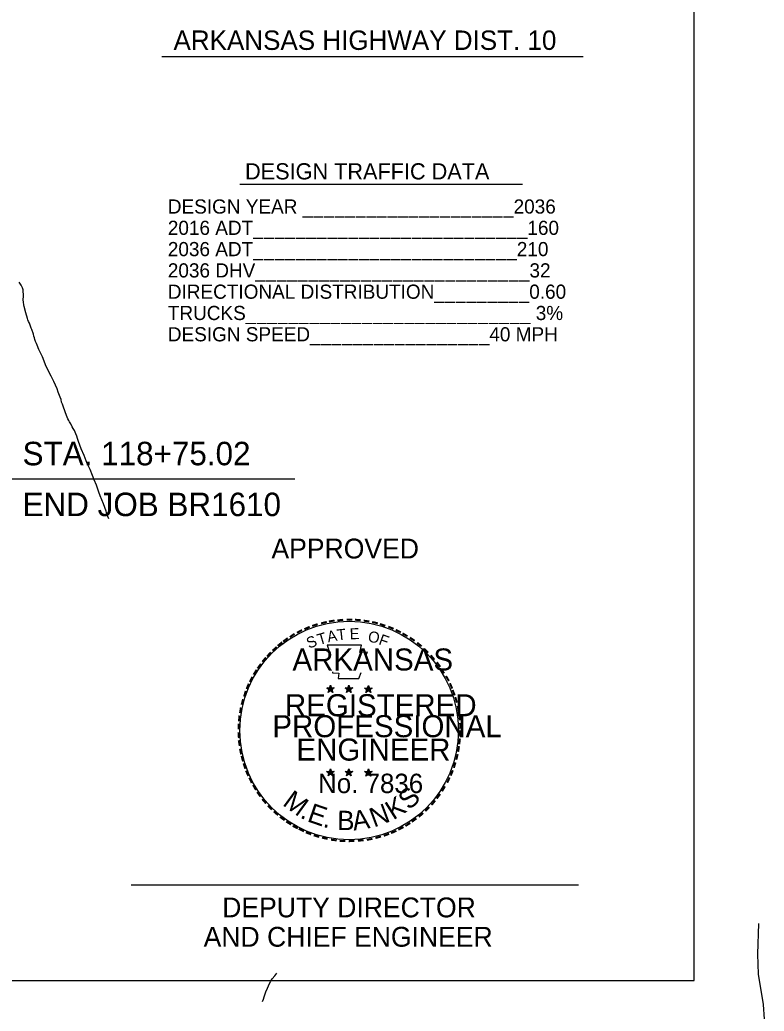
# Model space of a CAD drawing. Extents: x 1671357 to 13005564, y 567358 to 14261451.
# Drawn here: x 12758310.29 to 12758319.47, y 14259937.97 to 14259950.22 of the extents above; entities that cross this region are included whole.
import ezdxf

# ---------------------------------------------------------------- set-up
doc = ezdxf.new("R2010")
doc.units = 0
for name, color, linetype in [('32', 7, 'Continuous'), ('43', 7, 'Continuous'), ('Default', 7, 'Continuous'), ('R_Border PE', 7, 'Continuous')]:
    doc.layers.add(name, color=color, linetype=linetype)

msp = doc.modelspace()

# ---------------------------------------------------------------- linework, layer by layer
at = {"layer": '32'}
msp.add_lwpolyline([(12758313.281, 14259938.094), (12758313.294, 14259938.123), (12758313.303, 14259938.149), (12758313.311, 14259938.174), (12758313.323, 14259938.211), (12758313.344, 14259938.26), (12758313.355, 14259938.288), (12758313.382, 14259938.342), (12758313.403, 14259938.373), (12758313.436, 14259938.411), (12758313.459, 14259938.443)], dxfattribs=at)
at = {"layer": '43'}
msp.add_lwpolyline([(12758319.406, 14259939.056), (12758319.392, 14259938.677), (12758319.402, 14259938.43), (12758319.464, 14259938.058), (12758319.474, 14259937.874)], dxfattribs=at)
at = {"layer": 'Default'}
for p, q in [((12758318.61, 14259938.354), (12758318.61, 14259959.371)), ((12758312.04, 14259949.768), (12758317.239, 14259949.768)), ((12758313.002, 14259948.19), (12758316.492, 14259948.19)), ((12758310.042, 14259944.551), (12758313.682, 14259944.551)), ((12758284.583, 14259938.354), (12758318.61, 14259938.354))]:
    msp.add_line(p, q, dxfattribs=at)
for points in [[(12758310.977, 14259945.106), (12758310.969, 14259945.126), (12758310.96, 14259945.145), (12758310.947, 14259945.17), (12758310.933, 14259945.194), (12758310.917, 14259945.228), (12758310.901, 14259945.253), (12758310.891, 14259945.271), (12758310.881, 14259945.291), (12758310.865, 14259945.33), (12758310.847, 14259945.376), (12758310.821, 14259945.447), (12758310.814, 14259945.47), (12758310.802, 14259945.497), (12758310.796, 14259945.529), (12758310.787, 14259945.557), (12758310.761, 14259945.619), (12758310.747, 14259945.662), (12758310.729, 14259945.705), (12758310.708, 14259945.753), (12758310.673, 14259945.817), (12758310.614, 14259945.937), (12758310.566, 14259946.056), (12758310.523, 14259946.148), (12758310.501, 14259946.2), (12758310.493, 14259946.221), (12758310.482, 14259946.248), (12758310.473, 14259946.271), (12758310.467, 14259946.292), (12758310.46, 14259946.314), (12758310.454, 14259946.335), (12758310.435, 14259946.394), (12758310.429, 14259946.412), (12758310.424, 14259946.423), (12758310.406, 14259946.473), (12758310.396, 14259946.492), (12758310.387, 14259946.514), (12758310.382, 14259946.532), (12758310.363, 14259946.599), (12758310.342, 14259946.678), (12758310.338, 14259946.698), (12758310.332, 14259946.733), (12758310.33, 14259946.761), (12758310.33, 14259946.774), (12758310.331, 14259946.792), (12758310.332, 14259946.801), (12758310.332, 14259946.825), (12758310.33, 14259946.863), (12758310.327, 14259946.885), (12758310.323, 14259946.896), (12758310.319, 14259946.907), (12758310.311, 14259946.925), (12758310.302, 14259946.941), (12758310.278, 14259946.979)], [(12758311.244, 14259944.435), (12758311.232, 14259944.471), (12758311.204, 14259944.537), (12758311.183, 14259944.592), (12758311.154, 14259944.663), (12758311.119, 14259944.74), (12758311.082, 14259944.838), (12758311.045, 14259944.922), (12758311.013, 14259945.009), (12758311, 14259945.047), (12758310.99, 14259945.075), (12758310.977, 14259945.106)], [(12758311.385, 14259944.055), (12758311.375, 14259944.086), (12758311.369, 14259944.106), (12758311.357, 14259944.135), (12758311.351, 14259944.152), (12758311.32, 14259944.239), (12758311.28, 14259944.341), (12758311.262, 14259944.387), (12758311.244, 14259944.435)]]:
    msp.add_lwpolyline(points, dxfattribs=at)
at = {"layer": 'R_Border PE'}
for p, q in [((12758314.075, 14259941.966), (12758314.122, 14259941.951)), ((12758314.075, 14259941.966), (12758314.11, 14259941.96)), ((12758314.075, 14259941.966), (12758314.107, 14259941.949)), ((12758314.122, 14259942.001), (12758314.117, 14259941.966)), ((12758314.122, 14259941.951), (12758314.122, 14259942.001)), ((12758314.122, 14259942.001), (12758314.129, 14259941.967)), ((12758314.168, 14259941.966), (12758314.122, 14259941.951)), ((12758314.168, 14259941.966), (12758314.131, 14259941.959)), ((12758314.168, 14259941.966), (12758314.142, 14259941.952)), ((12758314.303, 14259941.966), (12758314.35, 14259941.951)), ((12758314.303, 14259941.966), (12758314.336, 14259941.96)), ((12758314.303, 14259941.966), (12758314.334, 14259941.949)), ((12758314.35, 14259942.001), (12758314.345, 14259941.966)), ((12758314.35, 14259941.951), (12758314.35, 14259942.001)), ((12758314.35, 14259942.001), (12758314.356, 14259941.967)), ((12758314.397, 14259941.966), (12758314.35, 14259941.951)), ((12758314.397, 14259941.966), (12758314.357, 14259941.959)), ((12758314.397, 14259941.966), (12758314.369, 14259941.952)), ((12758314.542, 14259941.965), (12758314.59, 14259941.949)), ((12758314.542, 14259941.965), (12758314.576, 14259941.958)), ((12758314.542, 14259941.965), (12758314.574, 14259941.948)), ((12758314.59, 14259941.998), (12758314.584, 14259941.965)), ((12758314.59, 14259941.949), (12758314.59, 14259941.998)), ((12758314.59, 14259941.998), (12758314.595, 14259941.965)), ((12758314.637, 14259941.965), (12758314.59, 14259941.949)), ((12758314.637, 14259941.965), (12758314.597, 14259941.958)), ((12758314.637, 14259941.965), (12758314.608, 14259941.951)), ((12758314.093, 14259941.91), (12758314.122, 14259941.951)), ((12758314.093, 14259941.91), (12758314.11, 14259941.944)), ((12758314.093, 14259941.91), (12758314.121, 14259941.939)), ((12758314.152, 14259941.91), (12758314.121, 14259941.939)), ((12758314.152, 14259941.91), (12758314.122, 14259941.951)), ((12758314.152, 14259941.91), (12758314.132, 14259941.949)), ((12758314.32, 14259941.91), (12758314.35, 14259941.951)), ((12758314.32, 14259941.91), (12758314.338, 14259941.944)), ((12758314.32, 14259941.91), (12758314.349, 14259941.939)), ((12758314.378, 14259941.91), (12758314.349, 14259941.939)), ((12758314.378, 14259941.91), (12758314.35, 14259941.951)), ((12758314.378, 14259941.91), (12758314.359, 14259941.949)), ((12758314.559, 14259941.909), (12758314.59, 14259941.949)), ((12758314.559, 14259941.909), (12758314.577, 14259941.942)), ((12758314.559, 14259941.909), (12758314.59, 14259941.938)), ((12758314.618, 14259941.909), (12758314.59, 14259941.949)), ((12758314.618, 14259941.909), (12758314.59, 14259941.938)), ((12758314.618, 14259941.909), (12758314.6, 14259941.948)), ((12758314.073, 14259940.936), (12758314.121, 14259940.92)), ((12758314.073, 14259940.936), (12758314.11, 14259940.929)), ((12758314.073, 14259940.936), (12758314.107, 14259940.919)), ((12758314.093, 14259940.88), (12758314.121, 14259940.92)), ((12758314.093, 14259940.88), (12758314.11, 14259940.913)), ((12758314.093, 14259940.88), (12758314.121, 14259940.91)), ((12758314.121, 14259940.969), (12758314.115, 14259940.936)), ((12758314.121, 14259940.92), (12758314.121, 14259940.969)), ((12758314.121, 14259940.969), (12758314.128, 14259940.936)), ((12758314.168, 14259940.936), (12758314.121, 14259940.92)), ((12758314.152, 14259940.88), (12758314.121, 14259940.92)), ((12758314.152, 14259940.88), (12758314.121, 14259940.909)), ((12758314.168, 14259940.936), (12758314.129, 14259940.929)), ((12758314.152, 14259940.88), (12758314.132, 14259940.919)), ((12758314.168, 14259940.936), (12758314.142, 14259940.922)), ((12758314.301, 14259940.936), (12758314.349, 14259940.92)), ((12758314.301, 14259940.936), (12758314.336, 14259940.929)), ((12758314.301, 14259940.936), (12758314.334, 14259940.919)), ((12758314.32, 14259940.88), (12758314.349, 14259940.92)), ((12758314.32, 14259940.88), (12758314.336, 14259940.913)), ((12758314.32, 14259940.88), (12758314.349, 14259940.91)), ((12758314.349, 14259940.969), (12758314.343, 14259940.936)), ((12758314.349, 14259940.92), (12758314.349, 14259940.969)), ((12758314.349, 14259940.969), (12758314.355, 14259940.936)), ((12758314.397, 14259940.936), (12758314.349, 14259940.92)), ((12758314.377, 14259940.88), (12758314.349, 14259940.92)), ((12758314.377, 14259940.88), (12758314.349, 14259940.909)), ((12758314.397, 14259940.936), (12758314.356, 14259940.929)), ((12758314.377, 14259940.88), (12758314.359, 14259940.919)), ((12758314.397, 14259940.936), (12758314.367, 14259940.922)), ((12758314.542, 14259940.934), (12758314.59, 14259940.919)), ((12758314.542, 14259940.934), (12758314.576, 14259940.927)), ((12758314.542, 14259940.934), (12758314.574, 14259940.917)), ((12758314.559, 14259940.878), (12758314.59, 14259940.919)), ((12758314.559, 14259940.878), (12758314.577, 14259940.912)), ((12758314.559, 14259940.878), (12758314.59, 14259940.909)), ((12758314.59, 14259940.968), (12758314.584, 14259940.934)), ((12758314.59, 14259940.919), (12758314.59, 14259940.968)), ((12758314.59, 14259940.968), (12758314.595, 14259940.934)), ((12758314.637, 14259940.934), (12758314.59, 14259940.919)), ((12758314.618, 14259940.878), (12758314.59, 14259940.919)), ((12758314.618, 14259940.878), (12758314.59, 14259940.908)), ((12758314.637, 14259940.934), (12758314.597, 14259940.927)), ((12758314.618, 14259940.878), (12758314.598, 14259940.917)), ((12758314.637, 14259940.934), (12758314.608, 14259940.92)), ((12758311.662, 14259939.536), (12758317.183, 14259939.536))]:
    msp.add_line(p, q, dxfattribs=at)
for points in [[(12758314.08, 14259942.494), (12758314.117, 14259942.38)], [(12758314.558, 14259942.369), (12758314.577, 14259942.407), (12758314.485, 14259942.404), (12758314.503, 14259942.494), (12758314.08, 14259942.494)], [(12758314.147, 14259942.165), (12758314.147, 14259942.152), (12758314.223, 14259942.149), (12758314.216, 14259942.085), (12758314.471, 14259942.085), (12758314.499, 14259942.158)], [(12758314.122, 14259942.001), (12758314.152, 14259941.91), (12758314.075, 14259941.966), (12758314.168, 14259941.966), (12758314.093, 14259941.91), (12758314.122, 14259942.001)], [(12758314.35, 14259942.001), (12758314.378, 14259941.91), (12758314.303, 14259941.966), (12758314.397, 14259941.966), (12758314.32, 14259941.91), (12758314.35, 14259942.001)], [(12758314.59, 14259941.998), (12758314.618, 14259941.909), (12758314.542, 14259941.965), (12758314.637, 14259941.965), (12758314.559, 14259941.909), (12758314.59, 14259941.998)], [(12758314.121, 14259940.969), (12758314.152, 14259940.88), (12758314.073, 14259940.936), (12758314.168, 14259940.936), (12758314.093, 14259940.88), (12758314.121, 14259940.969)], [(12758314.349, 14259940.969), (12758314.377, 14259940.88), (12758314.301, 14259940.936), (12758314.397, 14259940.936), (12758314.32, 14259940.88), (12758314.349, 14259940.969)], [(12758314.59, 14259940.968), (12758314.618, 14259940.878), (12758314.542, 14259940.934), (12758314.637, 14259940.934), (12758314.559, 14259940.878), (12758314.59, 14259940.968)]]:
    msp.add_lwpolyline(points, dxfattribs=at)
for centre, radius in [((12758314.352, 14259941.441), 1.35), ((12758314.121, 14259941.95), 0.0234), ((12758314.121, 14259941.95), 0.0197), ((12758314.121, 14259941.95), 0.0158), ((12758314.121, 14259941.95), 0.0135), ((12758314.121, 14259941.95), 0.0102), ((12758314.121, 14259941.95), 0.00674), ((12758314.121, 14259941.95), 0.00403), ((12758314.348, 14259941.95), 0.0234), ((12758314.348, 14259941.95), 0.0197), ((12758314.348, 14259941.95), 0.0158), ((12758314.348, 14259941.95), 0.0135), ((12758314.348, 14259941.95), 0.0102), ((12758314.348, 14259941.95), 0.00674), ((12758314.348, 14259941.95), 0.00403), ((12758314.588, 14259941.949), 0.0234), ((12758314.588, 14259941.949), 0.0197), ((12758314.588, 14259941.949), 0.0158), ((12758314.588, 14259941.949), 0.0135), ((12758314.588, 14259941.949), 0.0102), ((12758314.588, 14259941.949), 0.00674), ((12758314.588, 14259941.949), 0.00403), ((12758314.12, 14259940.92), 0.0234), ((12758314.12, 14259940.92), 0.0197), ((12758314.12, 14259940.92), 0.0158), ((12758314.12, 14259940.92), 0.0135), ((12758314.12, 14259940.92), 0.0102), ((12758314.12, 14259940.92), 0.00674), ((12758314.12, 14259940.92), 0.00403), ((12758314.348, 14259940.92), 0.0234), ((12758314.348, 14259940.92), 0.0197), ((12758314.348, 14259940.92), 0.0158), ((12758314.348, 14259940.92), 0.0135), ((12758314.348, 14259940.92), 0.0102), ((12758314.348, 14259940.92), 0.00674), ((12758314.348, 14259940.92), 0.00403), ((12758314.588, 14259940.918), 0.0234), ((12758314.588, 14259940.918), 0.0197), ((12758314.588, 14259940.918), 0.0158), ((12758314.588, 14259940.918), 0.0135), ((12758314.588, 14259940.918), 0.0102), ((12758314.588, 14259940.918), 0.00674), ((12758314.588, 14259940.918), 0.00403)]:
    msp.add_circle(centre, radius, dxfattribs=at)

# ---------------------------------------------------------------- texts
at = {"layer": 'Default'}
for s, height, p in [('ARKANSAS HIGHWAY DIST. 10', 0.24, (12758312.184, 14259949.848)), ('DESIGN TRAFFIC DATA', 0.2, (12758313.067, 14259948.248)), ('DESIGN YEAR ____________________2036', 0.175, (12758312.114, 14259947.826)), ('2016 ADT__________________________160', 0.175, (12758312.114, 14259947.563)), ('2036 ADT_________________________210', 0.175, (12758312.114, 14259947.3)), ('2036 DHV__________________________32', 0.175, (12758312.114, 14259947.037)), ('DIRECTIONAL DISTRIBUTION_________0.60', 0.175, (12758312.114, 14259946.774)), ('TRUCKS___________________________ 3%', 0.175, (12758312.114, 14259946.511)), ('DESIGN SPEED_________________40 MPH', 0.175, (12758312.114, 14259946.248)), ('STA. 118+75.02', 0.29, (12758310.321, 14259944.717)), ('END JOB BR1610', 0.29, (12758310.321, 14259944.089))]:
    msp.add_text(s, height=height, dxfattribs=at).set_placement(p)
at = {"layer": 'R_Border PE'}
for s, height, p in [('APPROVED', 0.245, (12758313.393, 14259943.566)), ('ARKANSAS', 0.2722, (12758313.652, 14259942.182)), ('REGISTERED', 0.2722, (12758313.559, 14259941.617)), ('PROFESSIONAL', 0.27219, (12758313.404, 14259941.358)), ('ENGINEER', 0.2722, (12758313.701, 14259941.069)), ('No. 7836', 0.2391, (12758313.968, 14259940.668)), ('DEPUTY DIRECTOR', 0.24497, (12758312.785, 14259939.133)), ('AND CHIEF ENGINEER', 0.24497, (12758312.556, 14259938.77))]:
    msp.add_text(s, height=height, dxfattribs=at).set_placement(p)
for s, height, rotation, p in [('-', 0.218, 10.2193, (12758314.104, 14259942.702)), ('-', 0.218, 5.8968, (12758314.203, 14259942.716)), ('-', 0.218, 0.1862, (12758314.308, 14259942.726)), ('-', 0.218, 357.743, (12758314.406, 14259942.725)), ('-', 0.218, 28.7918, (12758313.737, 14259942.568)), ('-', 0.218, 24.3072, (12758313.823, 14259942.611)), ('-', 0.218, 19.1761, (12758313.911, 14259942.648)), ('-', 0.218, 13.6301, (12758314.013, 14259942.68)), ('T', 0.136, 6.0228, (12758314.208, 14259942.553)), ('E', 0.136, 0.8323, (12758314.359, 14259942.568)), ('-', 0.218, 352.1617, (12758314.507, 14259942.716)), ('-', 0.218, 347.2049, (12758314.605, 14259942.702)), ('-', 0.218, 342.3362, (12758314.693, 14259942.68)), ('-', 0.218, 337.8551, (12758314.791, 14259942.651)), ('-', 0.218, 334.1211, (12758314.878, 14259942.614)), ('-', 0.218, 36.2317, (12758313.576, 14259942.464)), ('-', 0.218, 34.0636, (12758313.656, 14259942.518)), ('S', 0.136, 21.594, (12758313.856, 14259942.45)), ('T', 0.136, 16.4036, (12758313.981, 14259942.495)), ('A', 0.136, 11.2132, (12758314.093, 14259942.529)), ('O', 0.136, 350.4515, (12758314.577, 14259942.539)), ('F', 0.136, 340.0707, (12758314.707, 14259942.508)), ('-', 0.218, 329.6409, (12758314.957, 14259942.575)), ('-', 0.218, 325.8627, (12758315.044, 14259942.526)), ('-', 0.218, 42.9622, (12758313.454, 14259942.355)), ('-', 0.218, 38.9507, (12758313.513, 14259942.413)), ('-', 0.218, 320.5297, (12758315.128, 14259942.469)), ('-', 0.218, 315.5786, (12758315.209, 14259942.401)), ('-', 0.218, 50.6142, (12758313.337, 14259942.225)), ('-', 0.218, 48.4231, (12758313.393, 14259942.289)), ('-', 0.218, 309.8797, (12758315.286, 14259942.326)), ('-', 0.218, 54.2325, (12758313.282, 14259942.147)), ('-', 0.218, 306.6522, (12758315.359, 14259942.245)), ('-', 0.191, 303.6753, (12758315.423, 14259942.168)), ('-', 0.218, 62.8713, (12758313.194, 14259941.991)), ('-', 0.218, 58.0706, (12758313.237, 14259942.075)), ('-', 0.218, 299.6684, (12758315.468, 14259942.084)), ('-', 0.218, 67.7743, (12758313.159, 14259941.909)), ('-', 0.218, 294.6628, (12758315.513, 14259942.001)), ('-', 0.218, 72.3945, (12758313.131, 14259941.823)), ('-', 0.218, 290.5728, (12758315.546, 14259941.924)), ('-', 0.218, 285.1233, (12758315.578, 14259941.844)), ('-', 0.218, 81.2013, (12758313.086, 14259941.629)), ('-', 0.218, 75.461, (12758313.103, 14259941.725)), ('-', 0.218, 280.5493, (12758315.606, 14259941.742)), ('-', 0.218, 85.1863, (12758313.075, 14259941.535)), ('-', 0.218, 276.5962, (12758315.627, 14259941.64)), ('-', 0.218, 89.0622, (12758313.072, 14259941.44)), ('-', 0.218, 274.3301, (12758315.636, 14259941.54)), ('-', 0.218, 94.1959, (12758313.076, 14259941.34)), ('-', 0.218, 263.5172, (12758315.637, 14259941.364)), ('-', 0.218, 269.9407, (12758315.64, 14259941.454)), ('-', 0.218, 98.9479, (12758313.086, 14259941.251)), ('-', 0.218, 260.9953, (12758315.627, 14259941.274)), ('-', 0.218, 101.7149, (12758313.104, 14259941.15)), ('-', 0.218, 105.4578, (12758313.127, 14259941.069)), ('-', 0.218, 255.7626, (12758315.613, 14259941.182)), ('-', 0.218, 109.0874, (12758313.155, 14259940.983)), ('-', 0.218, 252.8681, (12758315.588, 14259941.084)), ('-', 0.218, 114.0643, (12758313.19, 14259940.902)), ('-', 0.218, 115.7289, (12758313.232, 14259940.818)), ('-', 0.218, 244.6197, (12758315.522, 14259940.908)), ('-', 0.218, 247.8887, (12758315.559, 14259940.993)), ('-', 0.218, 120.4471, (12758313.281, 14259940.738)), ('S', 0.239, 42.9205, (12758315.093, 14259940.449)), ('-', 0.218, 239.0712, (12758315.469, 14259940.805)), ('-', 0.218, 125.8934, (12758313.334, 14259940.663)), ('M', 0.239, 323.9056, (12758313.519, 14259940.525)), ('K', 0.239, 32.2382, (12758314.896, 14259940.329)), ('-', 0.218, 233.8452, (12758315.415, 14259940.717)), ('-', 0.218, 130.7181, (12758313.398, 14259940.585)), ('-', 0.218, 134.2238, (12758313.468, 14259940.513)), ('E', 0.239, 340.8881, (12758313.823, 14259940.322)), ('N', 0.239, 20.5042, (12758314.658, 14259940.241)), ('-', 0.218, 225.7653, (12758315.29, 14259940.563)), ('-', 0.218, 231.2538, (12758315.356, 14259940.639)), ('-', 0.218, 138.9338, (12758313.54, 14259940.45)), ('-', 0.218, 144.6463, (12758313.615, 14259940.394)), ('.', 0.239, 336.3407, (12758313.736, 14259940.367)), ('B', 0.239, 359.3149, (12758314.204, 14259940.212)), ('A', 0.239, 8.7702, (12758314.408, 14259940.204)), ('-', 0.218, 215.7363, (12758315.144, 14259940.43)), ('-', 0.218, 221.0851, (12758315.22, 14259940.493)), ('-', 0.218, 148.0898, (12758313.691, 14259940.343)), ('-', 0.218, 151.5704, (12758313.769, 14259940.298)), ('.', 0.239, 350.694, (12758314.021, 14259940.248)), ('-', 0.218, 207.3568, (12758314.996, 14259940.329)), ('-', 0.218, 212.2491, (12758315.073, 14259940.377)), ('-', 0.218, 154.6002, (12758313.842, 14259940.266)), ('-', 0.218, 158.5612, (12758313.926, 14259940.231)), ('-', 0.218, 162.7983, (12758314.02, 14259940.202)), ('-', 0.218, 167.5555, (12758314.117, 14259940.181)), ('-', 0.218, 195.4743, (12758314.735, 14259940.216)), ('-', 0.218, 200.7184, (12758314.828, 14259940.248)), ('-', 0.218, 204.2516, (12758314.912, 14259940.284)), ('-', 0.218, 173.1155, (12758314.222, 14259940.165)), ('-', 0.218, 176.5183, (12758314.324, 14259940.157)), ('-', 0.218, 181.5918, (12758314.426, 14259940.16)), ('-', 0.218, 185.8167, (12758314.535, 14259940.171)), ('-', 0.218, 191.2858, (12758314.636, 14259940.188))]:
    msp.add_text(s, height=height, rotation=rotation, dxfattribs=at).set_placement(p)

doc.saveas('drawing.dxf')
